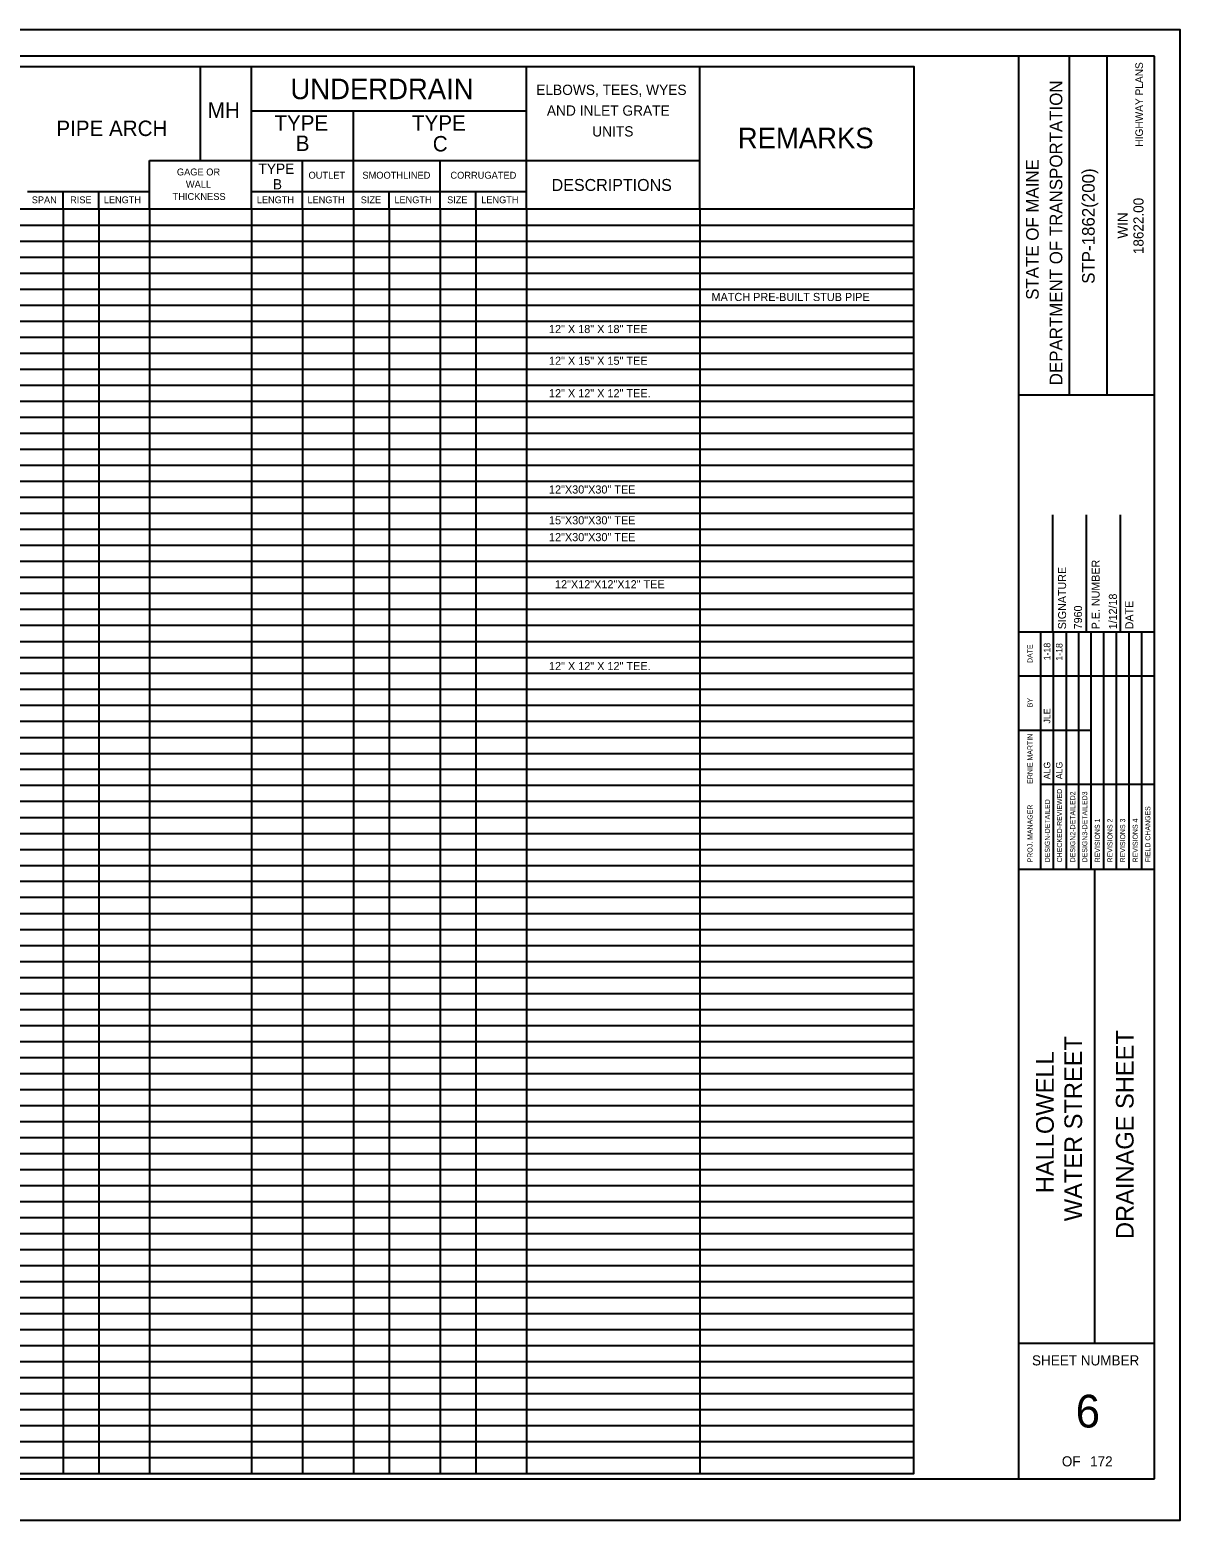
# Model space of a CAD drawing. Extents: x -0.13 to 2.7, y -0.05 to 1.78.
# Drawn here: x 1.283 to 2.698, y -0.051 to 1.782 of the extents above; entities that cross this region are included whole.
import ezdxf

# ---------------------------------------------------------------- set-up
doc = ezdxf.new("R2010")
doc.units = 0
for name, color, linetype in [('ANNOTATION', 7, 'Continuous'), ('BORDER', 7, 'Continuous'), ('PLOT BOUNDARY', 7, 'Continuous')]:
    doc.layers.add(name, color=color, linetype=linetype)

msp = doc.modelspace()

# ---------------------------------------------------------------- linework, layer by layer
at = {"layer": 'BORDER'}
for p, q in [((2.6667, 1.75), (0, 1.75)), ((2.5, 0), (2.5, 1.75)), ((2.5621, 1.3333), (2.5621, 1.75)), ((2.6087, 1.3333), (2.6087, 1.75)), ((2.6667, 0), (2.6667, 1.75)), ((1.4929, 1.6825), (1.4929, 1.7373)), ((1.5556, 1.6825), (1.5556, 1.7373)), ((1.8942, 1.6825), (1.8942, 1.7373)), ((2.1075, 1.6825), (2.1075, 1.7373)), ((1.4929, 1.6214), (1.4929, 1.6825)), ((1.5556, 1.6214), (1.5556, 1.6825)), ((1.5556, 1.6825), (1.6184, 1.6825)), ((1.6184, 1.6825), (1.7249, 1.6825)), ((1.6811, 1.6214), (1.6811, 1.6825)), ((1.7249, 1.6825), (1.7876, 1.6825)), ((1.7876, 1.6825), (1.8315, 1.6825)), ((1.8315, 1.6825), (1.8942, 1.6825)), ((1.8942, 1.6214), (1.8942, 1.6825)), ((2.1075, 1.6214), (2.1075, 1.6825)), ((1.4303, 1.5836), (1.4303, 1.6214)), ((1.4303, 1.6214), (1.5556, 1.6214)), ((1.5556, 1.5836), (1.5556, 1.6214)), ((1.5556, 1.6214), (1.6184, 1.6214)), ((1.6184, 1.5836), (1.6184, 1.6214)), ((1.6184, 1.6214), (1.7249, 1.6214)), ((1.6811, 1.5836), (1.6811, 1.6214)), ((1.7249, 1.6214), (1.8315, 1.6214)), ((1.7876, 1.5836), (1.7876, 1.6214)), ((1.8315, 1.6214), (1.8942, 1.6214)), ((1.8942, 1.5836), (1.8942, 1.6214)), ((1.8942, 1.6214), (2.1075, 1.6214)), ((2.1075, 1.5836), (2.1075, 1.6214)), ((1.2798, 1.5836), (1.3237, 1.5836)), ((1.3237, 1.5616), (1.3237, 1.5836)), ((1.3237, 1.5836), (1.3676, 1.5836)), ((1.3676, 1.5616), (1.3676, 1.5836)), ((1.3676, 1.5836), (1.4303, 1.5836)), ((1.4303, 1.5616), (1.4303, 1.5836)), ((1.5556, 1.5616), (1.5556, 1.5836)), ((1.5556, 1.5836), (1.6184, 1.5836)), ((1.6184, 1.5616), (1.6184, 1.5836)), ((1.6184, 1.5836), (1.6811, 1.5836)), ((1.6811, 1.5616), (1.6811, 1.5836)), ((1.6811, 1.5836), (1.7249, 1.5836)), ((1.7249, 1.5616), (1.7249, 1.5836)), ((1.7249, 1.5836), (1.7876, 1.5836)), ((1.7876, 1.5616), (1.7876, 1.5836)), ((1.7876, 1.5836), (1.8315, 1.5836)), ((1.8315, 1.5616), (1.8315, 1.5836)), ((1.8315, 1.5836), (1.8942, 1.5836)), ((1.8942, 1.5616), (1.8942, 1.5836)), ((2.1075, 1.5616), (2.1075, 1.5836)), ((1.3237, 1.5616), (1.3237, 0.0065)), ((1.3676, 1.5616), (1.3676, 0.0065)), ((1.4303, 1.5616), (1.4303, 0.0065)), ((1.5556, 1.5616), (1.5556, 0.0065)), ((1.6184, 1.5616), (1.6184, 0.0065)), ((1.6811, 1.5616), (1.6811, 0.0065)), ((1.7249, 1.5616), (1.7249, 0.0065)), ((1.7876, 1.5616), (1.7876, 0.0065)), ((1.8315, 1.5616), (1.8315, 0.0065)), ((1.8942, 1.5616), (1.8942, 0.0065)), ((2.1075, 1.5616), (2.1075, 0.0065)), ((0.1293, 1.5419), (2.3707, 1.5419)), ((0.1293, 1.5223), (2.3707, 1.5223)), ((0.1293, 1.5026), (2.3707, 1.5026)), ((0.1293, 1.4829), (2.3707, 1.4829)), ((0.1293, 1.4632), (2.3707, 1.4632)), ((0.1293, 1.4435), (2.3707, 1.4435)), ((0.1293, 1.4238), (2.3707, 1.4238)), ((0.1293, 1.4041), (2.3707, 1.4041)), ((0.1293, 1.3845), (2.3707, 1.3845)), ((0.1293, 1.3648), (2.3707, 1.3648)), ((0.1293, 1.3451), (2.3707, 1.3451)), ((0.1293, 1.3254), (2.3707, 1.3254)), ((2.5, 1.3332), (2.6667, 1.3332)), ((0.1293, 1.3057), (2.3707, 1.3057)), ((0.1293, 1.286), (2.3707, 1.286)), ((0.1293, 1.2664), (2.3707, 1.2664)), ((0.1293, 1.2467), (2.3707, 1.2467)), ((0.1293, 1.227), (2.3707, 1.227)), ((0.1293, 1.2073), (2.3707, 1.2073)), ((0.1293, 1.1876), (2.3707, 1.1876)), ((2.5417, 1.0417), (2.5417, 1.1858)), ((2.5833, 1.0417), (2.5833, 1.1858)), ((2.625, 1.0417), (2.625, 1.1858)), ((0.1293, 1.1679), (2.3707, 1.1679)), ((0.1293, 1.1482), (2.3707, 1.1482)), ((0.1293, 1.1286), (2.3707, 1.1286)), ((0.1293, 1.1089), (2.3707, 1.1089)), ((0.1293, 1.0892), (2.3707, 1.0892)), ((0.1293, 1.0695), (2.3707, 1.0695)), ((0.1293, 1.0498), (2.3707, 1.0498)), ((0.1293, 1.0301), (2.3707, 1.0301)), ((2.5, 1.0417), (2.6667, 1.0417)), ((0.1293, 1.0104), (2.3707, 1.0104)), ((0.1293, 0.9908), (2.3707, 0.9908)), ((0.1293, 0.9711), (2.3707, 0.9711)), ((0.1293, 0.9514), (2.3707, 0.9514)), ((0.1293, 0.9317), (2.3707, 0.9317)), ((0.1293, 0.912), (2.3707, 0.912)), ((0.1293, 0.8923), (2.3707, 0.8923)), ((0.1293, 0.8727), (2.3707, 0.8727)), ((0.1293, 0.853), (2.3707, 0.853)), ((0.1293, 0.8333), (2.3707, 0.8333)), ((0.1293, 0.8136), (2.3707, 0.8136)), ((0.1293, 0.7939), (2.3707, 0.7939)), ((0.1293, 0.7742), (2.3707, 0.7742)), ((0.1293, 0.7545), (2.3707, 0.7545)), ((0.1293, 0.7349), (2.3707, 0.7349)), ((2.5, 0.75), (2.6667, 0.75)), ((2.5932, 0.1667), (2.5932, 0.75)), ((0.1293, 0.7152), (2.3707, 0.7152)), ((0.1293, 0.6955), (2.3707, 0.6955)), ((0.1293, 0.6758), (2.3707, 0.6758)), ((0.1293, 0.6561), (2.3707, 0.6561)), ((0.1293, 0.6364), (2.3707, 0.6364)), ((0.1293, 0.6167), (2.3707, 0.6167)), ((0.1293, 0.5971), (2.3707, 0.5971)), ((0.1293, 0.5774), (2.3707, 0.5774)), ((0.1293, 0.5577), (2.3707, 0.5577)), ((0.1293, 0.538), (2.3707, 0.538)), ((0.1293, 0.5183), (2.3707, 0.5183)), ((0.1293, 0.4986), (2.3707, 0.4986)), ((0.1293, 0.479), (2.3707, 0.479)), ((0.1293, 0.4593), (2.3707, 0.4593)), ((0.1293, 0.4396), (2.3707, 0.4396)), ((0.1293, 0.4199), (2.3707, 0.4199)), ((0.1293, 0.4002), (2.3707, 0.4002)), ((0.1293, 0.3805), (2.3707, 0.3805)), ((0.1293, 0.3608), (2.3707, 0.3608)), ((0.1293, 0.3412), (2.3707, 0.3412)), ((0.1293, 0.3215), (2.3707, 0.3215)), ((0.1293, 0.3018), (2.3707, 0.3018)), ((0.1293, 0.2821), (2.3707, 0.2821)), ((0.1293, 0.2624), (2.3707, 0.2624)), ((0.1293, 0.2427), (2.3707, 0.2427)), ((0.1293, 0.223), (2.3707, 0.223)), ((0.1293, 0.2034), (2.3707, 0.2034)), ((0.1293, 0.1837), (2.3707, 0.1837)), ((2.5, 0.1667), (2.6667, 0.1667)), ((0.1293, 0.164), (2.3707, 0.164)), ((0.1293, 0.1443), (2.3707, 0.1443)), ((0.1293, 0.1246), (2.3707, 0.1246)), ((0.1293, 0.1049), (2.3707, 0.1049)), ((0.1293, 0.0853), (2.3707, 0.0853)), ((0.1293, 0.0656), (2.3707, 0.0656)), ((0.1293, 0.0459), (2.3707, 0.0459)), ((0.1293, 0.0262), (2.3707, 0.0262)), ((0, 0), (2.6667, 0)), ((0.1293, 0.0065), (2.3707, 0.0065))]:
    msp.add_line(p, q, dxfattribs=at)
msp.add_lwpolyline([(0.1293, 1.7373), (2.3707, 1.7373), (2.3707, 1.5616), (0.1293, 1.5616)], close=True, dxfattribs=at)
for points in [[(0.1293, 1.5616), (0.1293, 0.0065), (2.3707, 0.0065), (2.3707, 1.5616)], [(2.5269, 0.9875), (2.5269, 1.0417)], [(2.5269, 0.7501), (2.5269, 1.0299)], [(2.5425, 0.7501), (2.5425, 1.0417)], [(2.558, 1.0417), (2.558, 0.7501)], [(2.5735, 0.7501), (2.5735, 1.0417)], [(2.589, 0.7501), (2.589, 1.0417)], [(2.6046, 0.7501), (2.6046, 1.0417)], [(2.6201, 0.7501), (2.6201, 1.0417)], [(2.6356, 0.7501), (2.6356, 1.0417)], [(2.6512, 0.7501), (2.6512, 1.0417)], [(2.5, 0.9875), (2.6667, 0.9875)], [(2.5, 0.9209), (2.5269, 0.9209)], [(2.5269, 0.9209), (2.589, 0.9209)], [(2.5269, 0.8542), (2.6667, 0.8542)]]:
    msp.add_lwpolyline(points, dxfattribs=at)
at = {"layer": 'PLOT BOUNDARY'}
msp.add_lwpolyline([(-0.1349, -0.051), (2.6984, -0.051), (2.6984, 1.7823), (-0.1349, 1.7823)], close=True, dxfattribs=at)

# ---------------------------------------------------------------- texts
at = {"layer": 'ANNOTATION'}
for s, p in [('MATCH PRE-BUILT STUB PIPE', (2.1217, 1.4487)), ('12" X 18" X 18" TEE', (1.9217, 1.4093)), ('12" X 15" X 15" TEE', (1.9217, 1.3703)), ('12" X 12" X 12" TEE.', (1.9217, 1.3303)), ('12"X30"X30" TEE', (1.9217, 1.2119)), ('15"X30"X30" TEE', (1.9217, 1.174)), ('12"X30"X30" TEE', (1.9217, 1.1533)), ('12"X12"X12"X12" TEE', (1.9291, 1.0953)), ('12" X 12" X 12" TEE.', (1.9217, 0.9947))]:
    msp.add_text(s, height=0.01, dxfattribs=at).set_placement(p)
at = {"layer": 'BORDER'}
for s, height, p in [('HIGHWAY PLANS', 0.009317, (2.6526, 1.6386)), ('DEPARTMENT OF TRANSPORTATION', 0.015529, (2.5534, 1.3451)), ('STATE OF MAINE', 0.015529, (2.5243, 1.4502)), ('STP-1862(200)', 0.015529, (2.5932, 1.4699)), ('18622.00', 0.01242, (2.6533, 1.5064)), ('WIN', 0.01242, (2.6339, 1.5255)), ('SIGNATURE', 0.00984, (2.558, 1.0449)), ('P.E. NUMBER', 0.009843, (2.5993, 1.0449)), ('1/12/18', 0.00984, (2.6205, 1.0449)), ('7960', 0.00984, (2.5776, 1.0449)), ('DATE', 0.00984, (2.6407, 1.0449)), ('1-18', 0.00808, (2.5387, 1.0067)), ('1-18', 0.00808, (2.5536, 1.0063)), ('DATE', 0.00619, (2.5167, 1.0035)), ('BY', 0.00619, (2.5167, 0.949)), ('JLE', 0.00808, (2.5387, 0.929)), ('ERNIE MARTIN', 0.006212, (2.5167, 0.8549)), ('ALG', 0.00808, (2.5387, 0.8604)), ('ALG', 0.00808, (2.5536, 0.8604)), ('CHECKED-REVIEWED', 0.006212, (2.553, 0.7582)), ('PROJ. MANAGER', 0.006212, (2.5167, 0.7582)), ('DESIGN-DETAILED', 0.006212, (2.5381, 0.7582)), ('DESIGN2-DETAILED2', 0.006212, (2.5692, 0.7582)), ('DESIGN3-DETAILED3', 0.006212, (2.5841, 0.7582)), ('REVISIONS 1', 0.006212, (2.5996, 0.7582)), ('REVISIONS 2', 0.006212, (2.6151, 0.7582)), ('REVISIONS 3', 0.006212, (2.6307, 0.7582)), ('REVISIONS 4', 0.006212, (2.6462, 0.7582)), ('FIELD CHANGES', 0.006212, (2.6617, 0.7582)), ('DRAINAGE SHEET', 0.021738, (2.6411, 0.2949)), ('WATER STREET', 0.021738, (2.5777, 0.3168)), ('HALLOWELL', 0.02174, (2.5429, 0.3513))]:
    msp.add_text(s, height=height, rotation=90, dxfattribs=at).set_placement(p)
for s, height, p in [('UNDERDRAIN', 0.02528, (1.6035, 1.697)), ('ELBOWS, TEES, WYES', 0.012638, (1.906, 1.7022)), ('MH', 0.01896, (1.5018, 1.674)), ('AND INLET GRATE', 0.012638, (1.9191, 1.6767)), ('PIPE ARCH', 0.01896, (1.3155, 1.6517)), ('TYPE', 0.01896, (1.5838, 1.6583)), ('TYPE', 0.01896, (1.7531, 1.6583)), ('B', 0.019, (1.6101, 1.6333)), ('C', 0.019, (1.7787, 1.6327)), ('UNITS', 0.01264, (1.9749, 1.6511)), ('REMARKS', 0.02528, (2.154, 1.6366)), ('TYPE', 0.01264, (1.5642, 1.6051)), ('GAGE OR ', 0.00853, (1.4638, 1.6032)), ('WALL', 0.00853, (1.4749, 1.5881)), ('B', 0.0126, (1.5819, 1.5861)), ('OUTLET', 0.00853, (1.6258, 1.5992)), ('SMOOTHLINED', 0.008531, (1.6921, 1.5992)), ('CORRUGATED', 0.00853, (1.8004, 1.5992)), ('DESCRIPTIONS', 0.014744, (1.925, 1.5841)), ('SPAN', 0.00843, (1.2853, 1.569)), ('RISE', 0.00843, (1.3325, 1.569)), ('LENGTH', 0.00843, (1.3739, 1.569)), ('THICKNESS', 0.00853, (1.4585, 1.573)), ('LENGTH', 0.00843, (1.5622, 1.569)), ('LENGTH', 0.00843, (1.6245, 1.569)), ('SIZE', 0.00843, (1.6901, 1.569)), ('LENGTH', 0.00843, (1.7315, 1.569)), ('SIZE', 0.00843, (1.7964, 1.569)), ('LENGTH', 0.00843, (1.8384, 1.569)), ('SHEET NUMBER', 0.012421, (2.5161, 0.1394)), ('6', 0.0403, (2.5698, 0.063)), ('OF', 0.01242, (2.5528, 0.0152)), ('172', 0.01242, (2.5876, 0.0152))]:
    msp.add_text(s, height=height, dxfattribs=at).set_placement(p)

doc.saveas('drawing.dxf')
